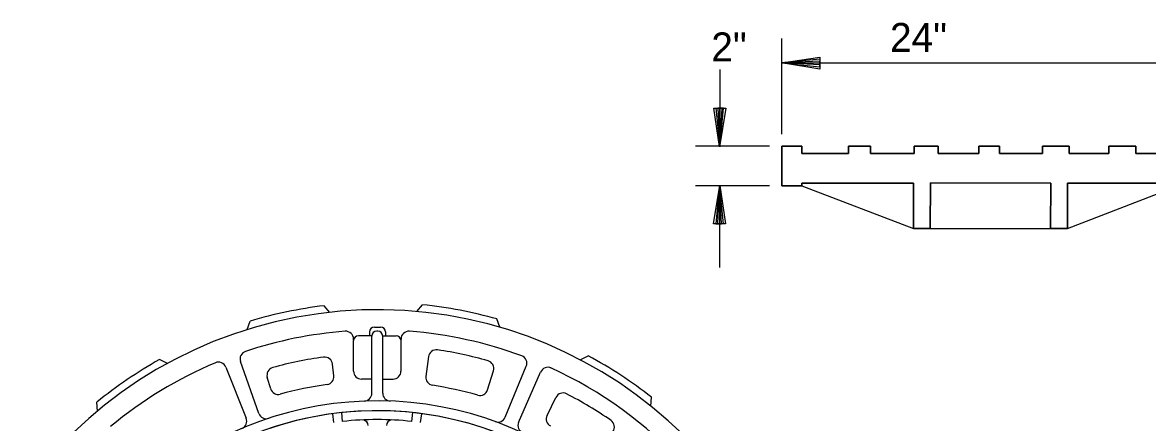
# Model space of a CAD drawing. Extents: x -7.1 to 10, y -5 to 6.
# Drawn here: x -5.508 to -2.543, y 1.576 to 2.631 of the extents above; entities that cross this region are included whole.
import ezdxf

# ---------------------------------------------------------------- set-up
doc = ezdxf.new("R2010")
doc.units = 0
for name, color, linetype in [('Level 1', 7, 'Continuous'), ('Level 11', 7, 'Continuous'), ('Level 13', 7, 'Continuous')]:
    doc.layers.add(name, color=color, linetype=linetype)

msp = doc.modelspace()

# ---------------------------------------------------------------- linework, layer by layer
at = {"layer": 'Level 1'}
for p, q in [((-4.6972, 1.8666), (-4.7126, 1.884)), ((-4.4683, 1.8687), (-4.4531, 1.8864)), ((-4.9152, 1.8212), (-4.9079, 1.8434)), ((-4.2496, 1.8272), (-4.2572, 1.8492)), ((-4.5931, 1.8148), (-4.5931, 1.8051)), ((-4.58, 1.8279), (-4.5637, 1.8279)), ((-4.5725, 1.8169), (-4.5725, 1.8169)), ((-4.5507, 1.8148), (-4.5507, 1.8051)), ((-4.635, 1.7114), (-4.635, 1.7921)), ((-4.6349, 1.7937), (-4.6349, 1.796)), ((-4.5868, 1.8051), (-4.622, 1.8051)), ((-4.5868, 1.6534), (-4.5868, 1.8039)), ((-4.5582, 1.8051), (-4.523, 1.8051)), ((-4.5582, 1.6534), (-4.5582, 1.8039)), ((-4.51, 1.7921), (-4.51, 1.796)), ((-4.51, 1.7114), (-4.51, 1.7921)), ((-4.4375, 1.7498), (-4.4444, 1.6976)), ((-4.0374, 1.7415), (-4.0165, 1.7521)), ((-5.1258, 1.7317), (-5.1467, 1.7419)), ((-4.9718, 1.7223), (-4.9181, 1.5874)), ((-4.8845, 1.6001), (-4.933, 1.7369)), ((-4.6868, 1.6993), (-4.6904, 1.7303)), ((-4.2354, 1.5902), (-4.1798, 1.7244)), ((-4.8535, 1.665), (-4.8625, 1.6949)), ((-4.5868, 1.6905), (-4.6142, 1.6905)), ((-4.5582, 1.6905), (-4.5309, 1.6905)), ((-4.282, 1.6621), (-4.2664, 1.7126)), ((-4.2001, 1.5762), (-4.142, 1.7093)), ((-4.1252, 1.5947), (-4.1019, 1.6424)), ((-3.8512, 1.6195), (-3.8497, 1.6427)), ((-5.3098, 1.6064), (-5.3116, 1.6297)), ((-4.6638, 1.5789), (-4.6662, 1.6022)), ((-4.4812, 1.5789), (-4.4787, 1.6022)), ((-4.6866, 1.5762), (-4.6897, 1.5994)), ((-4.4584, 1.5762), (-4.4553, 1.5994))]:
    msp.add_line(p, q, dxfattribs=at)
for centre, radius, start, end in [((-4.5726, 0.7218), 1.1516, 195.0717, 189.1227), ((-4.5731, 0.7221), 1.1703, 96.8462, 106.6251), ((-4.5729, 0.7223), 1.1703, 74.3462, 84.1251), ((-4.5725, 0.7217), 1.0983, 94.4323, 108.4426), ((-4.6558, 1.796), 0.0208, 0, 94.4323), ((-4.58, 1.8148), 0.013, 90, 180), ((-4.5738, 1.8039), 0.013, 90.0706, 180), ((-4.5725, 0.7218), 1.0951, 89.9327, 90.0706), ((-4.5712, 1.8039), 0.013, 0, 89.9327), ((-4.5637, 1.8148), 0.013, 0, 90), ((-4.4892, 1.796), 0.0208, 85.5661, 180), ((-4.5725, 0.7217), 1.0983, 69.7195, 85.5661), ((-4.622, 1.7921), 0.013, 90, 180), ((-4.523, 1.7921), 0.013, 0, 90), ((-4.9134, 1.7439), 0.0208, 108.4426, 199.522), ((-4.4169, 1.7471), 0.0208, 81.4682, 172.5206), ((-4.5703, 0.7246), 1.0548, 74.0594, 81.4682), ((-4.199, 1.7324), 0.0208, 337.5, 69.7195), ((-4.5727, 0.7224), 1.1703, 51.8462, 61.6251), ((-4.5731, 0.7218), 1.1703, 119.3462, 129.1251), ((-4.5725, 0.7217), 1.0983, 112.8646, 129.8224), ((-4.9912, 1.7145), 0.0208, 21.7281, 112.8646), ((-4.8425, 1.7008), 0.0208, 105.4191, 196.6639), ((-4.5725, 0.7218), 1.0365, 97.8463, 105.4191), ((-4.7111, 1.7279), 0.0208, 6.6622, 97.8463), ((-4.2863, 1.7188), 0.0208, 342.8232, 74.0594), ((-4.1229, 1.7009), 0.0208, 65.3438, 156.4401), ((-4.5725, 0.7217), 1.0983, 42.6463, 65.3654), ((-4.7075, 1.6969), 0.0208, 277.8841, 6.6622), ((-4.6142, 1.7114), 0.0208, 180, 270), ((-4.5309, 1.7114), 0.0208, 270, 0), ((-4.4237, 1.6949), 0.0208, 172.5206, 261.307), ((-4.8336, 1.6709), 0.0208, 196.6639, 285.3801), ((-4.5725, 0.7218), 0.9635, 97.8841, 105.3801), ((-4.5725, 0.7218), 0.9635, 74.0447, 81.307), ((-4.3019, 1.6683), 0.0208, 254.0447, 342.8232), ((-4.5725, 0.7218), 0.9115, 12.3185, 171.9696), ((-4.6077, 1.6534), 0.0208, 272.163, 0), ((-4.5374, 1.6534), 0.0208, 180, 267.8408), ((-4.0832, 1.6333), 0.0208, 62.7853, 153.8952), ((-4.556, 0.7137), 1.0548, 55.3597, 62.7853), ((-4.5725, 0.7218), 0.8854, 5.6674, 175.3947), ((-4.5725, 0.7218), 0.8854, 5.6674, 126.7344), ((-4.9374, 1.5797), 0.0208, 293.0438, 21.7281), ((-4.8649, 1.607), 0.0208, 199.522, 288.2762), ((-4.5725, 0.7218), 0.862, 83.922, 96.078), ((-4.6121, 1.5676), 0.0156, 1.611, 78.8242), ((-4.5328, 1.5676), 0.0156, 101.1758, 178.389), ((-4.2546, 1.5982), 0.0208, 250.0635, 337.5), ((-4.181, 1.5679), 0.0208, 156.4401, 245.168), ((-4.1065, 1.5856), 0.0208, 153.8952, 242.6906), ((-3.9683, 1.5644), 0.0208, 324.2052, 55.3597)]:
    msp.add_arc(centre, radius, start, end, dxfattribs=at)
at = {"layer": 'Level 11'}
for p, q in [((-3.5064, 2.3365), (-3.5064, 2.5884)), ((-3.5064, 2.5243), (-2.4168, 2.5243)), ((-3.67, 2.507), (-3.67, 2.3044)), ((-3.5385, 2.3044), (-3.7342, 2.3044)), ((-3.5385, 2.2002), (-3.7342, 2.2002)), ((-3.67, 1.9849), (-3.67, 2.2002)), ((-3.4533, 2.2002), (-3.1593, 2.0879)), ((-2.7537, 2.0879), (-2.4624, 2.2002)), ((-3.115, 2.0879), (-2.798, 2.0879))]:
    msp.add_line(p, q, dxfattribs=at)
for points in [[(-2.4624, 2.2073), (-2.7537, 2.2073), (-2.7537, 2.0879), (-2.798, 2.0879), (-2.7971, 2.2075), (-3.1147, 2.2082), (-3.115, 2.0879), (-3.1593, 2.0879), (-3.1593, 2.2073), (-3.4533, 2.2073), (-3.4533, 2.2002), (-3.5064, 2.2002), (-3.5064, 2.3044), (-3.4533, 2.3044), (-3.4533, 2.285), (-3.3303, 2.285), (-3.3303, 2.3044), (-3.2727, 2.3044), (-3.2727, 2.285), (-3.1574, 2.285), (-3.1574, 2.3044), (-3.094, 2.3044), (-3.094, 2.285), (-2.9869, 2.285), (-2.9869, 2.3044), (-2.9325, 2.3044), (-2.9325, 2.285), (-2.8197, 2.285), (-2.8197, 2.3044), (-2.7491, 2.3044), (-2.7491, 2.285), (-2.6444, 2.285), (-2.6444, 2.3044), (-2.5737, 2.3044), (-2.5737, 2.285), (-2.4624, 2.285)], [(-2.4624, 2.285), (-2.5737, 2.285), (-2.5737, 2.3044), (-2.6444, 2.3044), (-2.6444, 2.285), (-2.7491, 2.285), (-2.7491, 2.3044), (-2.8197, 2.3044), (-2.8197, 2.285), (-2.9325, 2.285), (-2.9325, 2.3044), (-2.9869, 2.3044), (-2.9869, 2.285), (-3.094, 2.285), (-3.094, 2.3044), (-3.1574, 2.3044), (-3.1574, 2.285), (-3.2727, 2.285), (-3.2727, 2.3044), (-3.3303, 2.3044), (-3.3303, 2.285), (-3.4533, 2.285), (-3.4533, 2.3044), (-3.5064, 2.3044), (-3.5064, 2.2002), (-3.4533, 2.2002), (-3.4533, 2.2073), (-3.1593, 2.2073), (-3.1593, 2.0879), (-3.115, 2.0879), (-3.1147, 2.2082), (-2.7971, 2.2075), (-2.798, 2.0879), (-2.7537, 2.0879), (-2.7537, 2.2073), (-2.4624, 2.2073)]]:
    msp.add_lwpolyline(points, dxfattribs=at)
at = {"layer": 'Level 13'}
for p, q in [((-3.4058, 2.5343), (-3.5076, 2.5241)), ((-3.5076, 2.5241), (-3.4058, 2.5241)), ((-3.4058, 2.519), (-3.5076, 2.5241)), ((-3.5076, 2.5241), (-3.4058, 2.5139)), ((-3.4058, 2.5078), (-3.5075, 2.5244)), ((-3.5071, 2.5247), (-3.4058, 2.5393)), ((-3.4058, 2.5292), (-3.5026, 2.5241)), ((-3.4058, 2.5393), (-3.4058, 2.5078)), ((-3.4058, 2.5139), (-3.4058, 2.5292)), ((-3.4058, 2.5241), (-3.4058, 2.519)), ((-3.6705, 2.3036), (-3.6851, 2.405)), ((-3.6851, 2.405), (-3.6536, 2.405)), ((-3.68, 2.4049), (-3.6699, 2.3031)), ((-3.6597, 2.4049), (-3.675, 2.4049)), ((-3.675, 2.4049), (-3.6699, 2.3082)), ((-3.6536, 2.405), (-3.6702, 2.3032)), ((-3.6699, 2.3031), (-3.6699, 2.4049)), ((-3.6699, 2.4049), (-3.6648, 2.4049)), ((-3.6648, 2.4049), (-3.6699, 2.3031)), ((-3.6699, 2.3031), (-3.6597, 2.4049)), ((-3.6865, 2.0996), (-3.6699, 2.2013)), ((-3.6702, 2.2015), (-3.6804, 2.0996)), ((-3.6753, 2.0996), (-3.6702, 2.2015)), ((-3.66, 2.0996), (-3.6702, 2.2015)), ((-3.6702, 2.2015), (-3.6702, 2.0996)), ((-3.6651, 2.0996), (-3.6702, 2.1964)), ((-3.6695, 2.201), (-3.6549, 2.0996)), ((-3.6549, 2.0996), (-3.6865, 2.0996)), ((-3.6804, 2.0996), (-3.6651, 2.0996)), ((-3.6702, 2.0996), (-3.6753, 2.0996))]:
    msp.add_line(p, q, dxfattribs=at)

# ---------------------------------------------------------------- texts
at = {"layer": 'Level 11'}
for s, p in [('24"', (-3.2212, 2.5531)), ('2"', (-3.6921, 2.5281))]:
    msp.add_text(s, height=0.07651, dxfattribs=at).set_placement(p)

doc.saveas('drawing.dxf')
